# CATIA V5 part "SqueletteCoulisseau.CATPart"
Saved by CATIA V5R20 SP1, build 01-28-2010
Part number: SqueletteCoulisseau
Publications: "LargeurCoulisseau", "EpaisseurCoulisseau", "Point.1", "Droite.1", "Point.2", "Point.3", "Point.4", "Point.5", "Droite.2", "Droite.3", "Droite.4", "Droite.5", "LongueurCoulisseau"
Bounding box of the stored display mesh (mm): x -20 to 20, y -20 to 20, z -10 to 10
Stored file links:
  C:\Documents and Settings\ndumont\Bureau\ndumont_CAO\SqueletteCoulisseau.CATPart
  J:\Rendus\Rendu_IAO\ndumont_CAO\Squelette.CATProduct
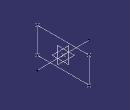
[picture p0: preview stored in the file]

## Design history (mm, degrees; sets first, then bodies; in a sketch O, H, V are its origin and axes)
Parameters
  LongueurCoulisseau = 40 mm
  LargeurCoulisseau = 20 mm
  EpaisseurCoulisseau = 20 mm
Set1
  Point1: (0, 0, 0)
  Line1: type Normal, RefPoint Point1, RefSkin yz-plane, Start -20, End 20
  Point2: (0, -20 {= -LongueurCoulisseau /2}, 10 {= LargeurCoulisseau /2})
  Point3: (0, 20 {= LongueurCoulisseau /2}, 10 {= LargeurCoulisseau /2})
  Point4: (0, 20, -10 {= -LargeurCoulisseau /2})
  Point5: (0, -20 {= -LongueurCoulisseau /2}, -10 {= -LargeurCoulisseau /2})
  Line2: type PtPt, FirstPoint Point2, SecondPoint Point3
  Line3: type PtPt, FirstPoint Point3, SecondPoint Point4
  Line4: type PtPt, FirstPoint Point4, SecondPoint Point5
  Line5: type PtPt, FirstPoint Point5, SecondPoint Point2
Body1 (main body)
